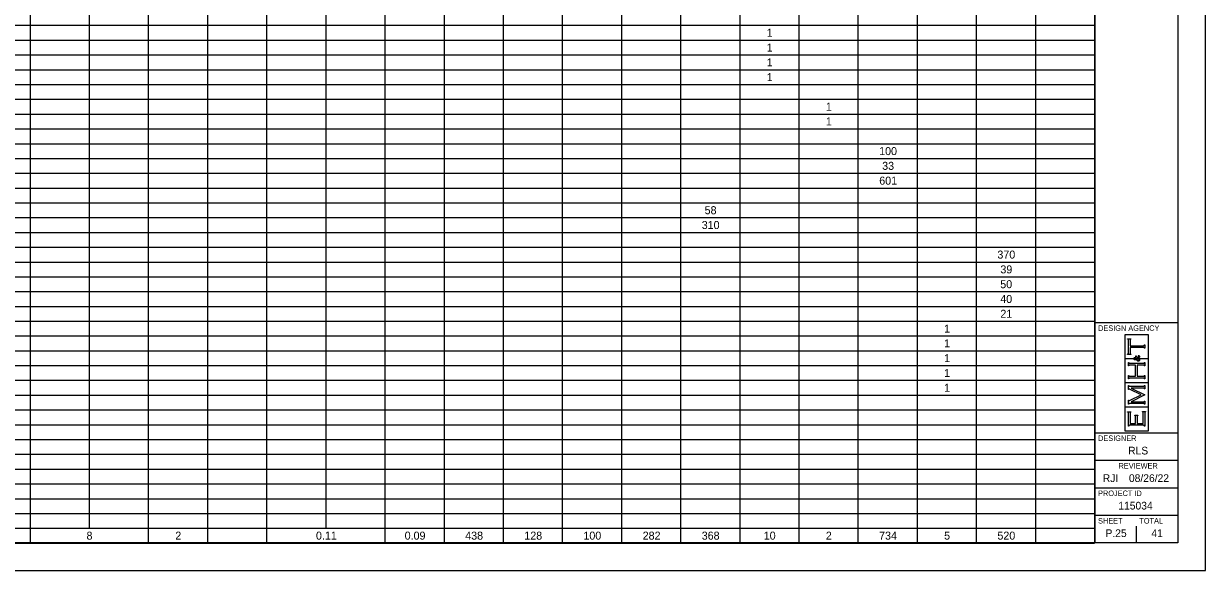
# Model space of a CAD drawing. Extents: x 0 to 34, y 0 to 22.
# Drawn here: x 12.53 to 34, y 0 to 9.93 of the extents above; entities that cross this region are included whole.
import ezdxf

# ---------------------------------------------------------------- set-up
doc = ezdxf.new("R2010")
doc.units = 0
for name, color, linetype in [('SH_Border', 7, 'Continuous'), ('SH_Cut_Line', 7, 'Continuous'), ('SH_Data', 7, 'Continuous'), ('SH_Text', 7, 'Continuous')]:
    doc.layers.add(name, color=color, linetype=linetype)

msp = doc.modelspace()

# ---------------------------------------------------------------- linework, layer by layer
at = {"layer": 'SH_Border'}
for p, q in [((32, 0.5), (32, 21.5)), ((32, 4.5), (33.5, 4.5)), ((32, 2.5), (33.5, 2.5)), ((32, 2), (33.5, 2)), ((32, 1.5), (33.5, 1.5)), ((32, 1), (33.5, 1))]:
    msp.add_line(p, q, dxfattribs=at)
msp.add_lwpolyline([(1.5, 21.5), (33.5, 21.5), (33.5, 0.5), (1.5, 0.5)], close=True, dxfattribs=at)
at = {"layer": 'SH_Cut_Line'}
msp.add_lwpolyline([(0, 0), (34, 0), (34, 22), (0, 22)], close=True, dxfattribs=at)
at = {"layer": 'SH_Data'}
for p, q in [((32.966, 4.28), (32.534, 4.28)), ((32.534, 4.28), (32.534, 3.848)), ((32.588, 4.199), (32.588, 4.206)), ((32.588, 4.206), (32.644, 4.206)), ((32.594, 4.198), (32.588, 4.199)), ((32.598, 4.196), (32.594, 4.198)), ((32.599, 4.194), (32.598, 4.196)), ((32.601, 4.191), (32.599, 4.194)), ((32.602, 4.187), (32.601, 4.191)), ((32.602, 4.181), (32.602, 4.187)), ((32.602, 3.947), (32.602, 4.181)), ((32.632, 4.191), (32.631, 4.187)), ((32.631, 4.187), (32.631, 4.181)), ((32.631, 4.181), (32.631, 4.081)), ((32.631, 4.081), (32.872, 4.081)), ((32.633, 4.194), (32.632, 4.191)), ((32.635, 4.196), (32.633, 4.194)), ((32.639, 4.198), (32.635, 4.196)), ((32.644, 4.199), (32.639, 4.198)), ((32.644, 4.206), (32.644, 4.199)), ((32.872, 4.081), (32.878, 4.081)), ((32.878, 4.081), (32.882, 4.082)), ((32.882, 4.082), (32.885, 4.084)), ((32.885, 4.084), (32.887, 4.085)), ((32.887, 4.085), (32.889, 4.089)), ((32.889, 4.089), (32.891, 4.095)), ((32.891, 4.095), (32.898, 4.095)), ((32.898, 4.095), (32.898, 4.033)), ((32.966, 3.848), (32.966, 4.28)), ((32.588, 3.928), (32.594, 3.93)), ((32.588, 3.921), (32.588, 3.928)), ((32.644, 3.921), (32.588, 3.921)), ((32.594, 3.93), (32.598, 3.932)), ((32.598, 3.932), (32.599, 3.934)), ((32.599, 3.934), (32.601, 3.937)), ((32.601, 3.937), (32.602, 3.941)), ((32.602, 3.941), (32.602, 3.947)), ((32.872, 4.047), (32.631, 4.047)), ((32.631, 4.047), (32.631, 3.947)), ((32.631, 3.947), (32.631, 3.941)), ((32.631, 3.941), (32.632, 3.937)), ((32.632, 3.937), (32.633, 3.934)), ((32.633, 3.934), (32.635, 3.932)), ((32.635, 3.932), (32.639, 3.93)), ((32.639, 3.93), (32.644, 3.928)), ((32.644, 3.928), (32.644, 3.921)), ((32.71, 3.864), (32.714, 3.866)), ((32.714, 3.866), (32.719, 3.866)), ((32.719, 3.866), (32.724, 3.866)), ((32.724, 3.866), (32.728, 3.864)), ((32.738, 3.867), (32.738, 3.898)), ((32.738, 3.898), (32.741, 3.898)), ((32.741, 3.867), (32.738, 3.867)), ((32.741, 3.898), (32.741, 3.894)), ((32.741, 3.894), (32.742, 3.891)), ((32.742, 3.871), (32.741, 3.869)), ((32.741, 3.869), (32.741, 3.867)), ((32.742, 3.891), (32.744, 3.889)), ((32.743, 3.872), (32.742, 3.871)), ((32.745, 3.873), (32.743, 3.872)), ((32.744, 3.889), (32.745, 3.887)), ((32.745, 3.887), (32.75, 3.883)), ((32.747, 3.874), (32.745, 3.873)), ((32.749, 3.874), (32.747, 3.874)), ((32.756, 3.874), (32.749, 3.874)), ((32.75, 3.883), (32.757, 3.879)), ((32.764, 3.87), (32.756, 3.874)), ((32.757, 3.879), (32.765, 3.875)), ((32.775, 3.861), (32.764, 3.87)), ((32.765, 3.875), (32.772, 3.87)), ((32.772, 3.87), (32.779, 3.865)), ((32.779, 3.865), (32.784, 3.869)), ((32.781, 3.9), (32.783, 3.902)), ((32.785, 3.899), (32.781, 3.9)), ((32.783, 3.902), (32.79, 3.901)), ((32.784, 3.869), (32.787, 3.873)), ((32.788, 3.897), (32.785, 3.899)), ((32.787, 3.873), (32.789, 3.876)), ((32.789, 3.895), (32.788, 3.897)), ((32.791, 3.892), (32.789, 3.895)), ((32.789, 3.876), (32.791, 3.88)), ((32.79, 3.901), (32.795, 3.898)), ((32.792, 3.89), (32.791, 3.892)), ((32.791, 3.88), (32.792, 3.883)), ((32.792, 3.886), (32.792, 3.89)), ((32.792, 3.883), (32.792, 3.886)), ((32.795, 3.898), (32.799, 3.894)), ((32.8, 3.868), (32.798, 3.864)), ((32.799, 3.894), (32.802, 3.89)), ((32.802, 3.872), (32.8, 3.868)), ((32.802, 3.89), (32.803, 3.885)), ((32.803, 3.876), (32.802, 3.872)), ((32.803, 3.885), (32.803, 3.88)), ((32.803, 3.88), (32.803, 3.876)), ((32.878, 4.047), (32.872, 4.047)), ((32.883, 4.046), (32.878, 4.047)), ((32.885, 4.044), (32.883, 4.046)), ((32.888, 4.042), (32.885, 4.044)), ((32.889, 4.039), (32.888, 4.042)), ((32.891, 4.033), (32.889, 4.039)), ((32.898, 4.033), (32.891, 4.033)), ((32.534, 3.848), (32.693, 3.848)), ((32.693, 3.842), (32.534, 3.842)), ((32.534, 3.842), (32.534, 3.41)), ((32.602, 3.714), (32.602, 3.776)), ((32.602, 3.776), (32.609, 3.776)), ((32.609, 3.714), (32.602, 3.714)), ((32.609, 3.776), (32.611, 3.77)), ((32.61, 3.72), (32.609, 3.714)), ((32.612, 3.723), (32.61, 3.72)), ((32.611, 3.77), (32.612, 3.766)), ((32.612, 3.766), (32.615, 3.765)), ((32.615, 3.725), (32.612, 3.723)), ((32.615, 3.765), (32.617, 3.763)), ((32.617, 3.727), (32.615, 3.725)), ((32.617, 3.763), (32.622, 3.762)), ((32.622, 3.728), (32.617, 3.727)), ((32.622, 3.762), (32.628, 3.762)), ((32.628, 3.728), (32.622, 3.728)), ((32.628, 3.762), (32.872, 3.762)), ((32.732, 3.728), (32.628, 3.728)), ((32.693, 3.848), (32.693, 3.842)), ((32.701, 3.852), (32.703, 3.857)), ((32.701, 3.846), (32.701, 3.852)), ((32.701, 3.84), (32.701, 3.846)), ((32.703, 3.835), (32.701, 3.84)), ((32.703, 3.857), (32.706, 3.861)), ((32.706, 3.83), (32.703, 3.835)), ((32.706, 3.861), (32.71, 3.864)), ((32.707, 3.852), (32.706, 3.849)), ((32.706, 3.849), (32.706, 3.846)), ((32.706, 3.846), (32.706, 3.842)), ((32.706, 3.842), (32.708, 3.839)), ((32.71, 3.824), (32.706, 3.83)), ((32.71, 3.854), (32.707, 3.852)), ((32.708, 3.839), (32.711, 3.837)), ((32.712, 3.856), (32.71, 3.854)), ((32.717, 3.821), (32.71, 3.824)), ((32.711, 3.837), (32.714, 3.835)), ((32.715, 3.857), (32.712, 3.856)), ((32.714, 3.835), (32.716, 3.834)), ((32.718, 3.857), (32.715, 3.857)), ((32.716, 3.834), (32.719, 3.834)), ((32.725, 3.821), (32.717, 3.821)), ((32.723, 3.857), (32.718, 3.857)), ((32.719, 3.834), (32.722, 3.834)), ((32.722, 3.834), (32.724, 3.834)), ((32.727, 3.856), (32.723, 3.857)), ((32.724, 3.834), (32.727, 3.835)), ((32.728, 3.821), (32.725, 3.821)), ((32.73, 3.853), (32.727, 3.856)), ((32.727, 3.835), (32.73, 3.836)), ((32.728, 3.864), (32.732, 3.861)), ((32.731, 3.822), (32.728, 3.821)), ((32.734, 3.85), (32.73, 3.853)), ((32.73, 3.836), (32.734, 3.837)), ((32.734, 3.822), (32.731, 3.822)), ((32.732, 3.861), (32.736, 3.857)), ((32.732, 3.525), (32.732, 3.728)), ((32.737, 3.845), (32.734, 3.85)), ((32.734, 3.837), (32.74, 3.839)), ((32.737, 3.823), (32.734, 3.822)), ((32.736, 3.857), (32.74, 3.851)), ((32.74, 3.839), (32.737, 3.845)), ((32.741, 3.825), (32.737, 3.823)), ((32.74, 3.851), (32.745, 3.842)), ((32.746, 3.827), (32.741, 3.825)), ((32.745, 3.842), (32.755, 3.848)), ((32.753, 3.815), (32.746, 3.827)), ((32.757, 3.832), (32.751, 3.829)), ((32.751, 3.829), (32.755, 3.824)), ((32.759, 3.808), (32.753, 3.815)), ((32.755, 3.848), (32.765, 3.855)), ((32.755, 3.824), (32.758, 3.819)), ((32.762, 3.835), (32.757, 3.832)), ((32.758, 3.819), (32.762, 3.817)), ((32.765, 3.803), (32.759, 3.808)), ((32.872, 3.728), (32.76, 3.728)), ((32.76, 3.728), (32.76, 3.525)), ((32.766, 3.838), (32.762, 3.835)), ((32.762, 3.817), (32.766, 3.814)), ((32.765, 3.855), (32.775, 3.861)), ((32.77, 3.799), (32.765, 3.803)), ((32.77, 3.84), (32.766, 3.838)), ((32.766, 3.814), (32.771, 3.812)), ((32.776, 3.845), (32.77, 3.84)), ((32.776, 3.797), (32.77, 3.799)), ((32.771, 3.812), (32.775, 3.812)), ((32.775, 3.812), (32.78, 3.812)), ((32.785, 3.851), (32.776, 3.845)), ((32.782, 3.797), (32.776, 3.797)), ((32.78, 3.812), (32.785, 3.814)), ((32.788, 3.797), (32.782, 3.797)), ((32.789, 3.846), (32.785, 3.851)), ((32.785, 3.814), (32.789, 3.817)), ((32.793, 3.8), (32.788, 3.797)), ((32.794, 3.859), (32.789, 3.855)), ((32.789, 3.855), (32.795, 3.849)), ((32.792, 3.842), (32.789, 3.846)), ((32.789, 3.817), (32.793, 3.821)), ((32.793, 3.839), (32.792, 3.842)), ((32.794, 3.837), (32.793, 3.839)), ((32.793, 3.821), (32.795, 3.825)), ((32.797, 3.804), (32.793, 3.8)), ((32.798, 3.864), (32.794, 3.859)), ((32.795, 3.834), (32.794, 3.837)), ((32.795, 3.849), (32.798, 3.843)), ((32.795, 3.831), (32.795, 3.834)), ((32.795, 3.825), (32.795, 3.831)), ((32.801, 3.809), (32.797, 3.804)), ((32.798, 3.843), (32.8, 3.839)), ((32.8, 3.839), (32.802, 3.834)), ((32.803, 3.815), (32.801, 3.809)), ((32.802, 3.834), (32.803, 3.829)), ((32.807, 3.842), (32.803, 3.848)), ((32.803, 3.848), (32.966, 3.848)), ((32.803, 3.829), (32.803, 3.823)), ((32.803, 3.823), (32.803, 3.815)), ((32.966, 3.842), (32.807, 3.842)), ((32.872, 3.762), (32.878, 3.762)), ((32.878, 3.728), (32.872, 3.728)), ((32.878, 3.762), (32.882, 3.763)), ((32.883, 3.727), (32.878, 3.728)), ((32.882, 3.763), (32.885, 3.765)), ((32.885, 3.725), (32.883, 3.727)), ((32.885, 3.765), (32.887, 3.766)), ((32.888, 3.723), (32.885, 3.725)), ((32.887, 3.766), (32.889, 3.77)), ((32.889, 3.72), (32.888, 3.723)), ((32.889, 3.77), (32.891, 3.776)), ((32.891, 3.714), (32.889, 3.72)), ((32.891, 3.776), (32.898, 3.776)), ((32.898, 3.714), (32.891, 3.714)), ((32.898, 3.776), (32.898, 3.714)), ((32.966, 3.41), (32.966, 3.842)), ((32.602, 3.477), (32.602, 3.538)), ((32.602, 3.538), (32.609, 3.538)), ((32.609, 3.477), (32.602, 3.477)), ((32.609, 3.538), (32.611, 3.533)), ((32.61, 3.482), (32.609, 3.477)), ((32.612, 3.486), (32.61, 3.482)), ((32.611, 3.533), (32.612, 3.529)), ((32.612, 3.529), (32.615, 3.527)), ((32.615, 3.488), (32.612, 3.486)), ((32.615, 3.527), (32.617, 3.526)), ((32.617, 3.49), (32.615, 3.488)), ((32.617, 3.526), (32.622, 3.525)), ((32.622, 3.491), (32.617, 3.49)), ((32.622, 3.525), (32.628, 3.525)), ((32.628, 3.491), (32.622, 3.491)), ((32.628, 3.525), (32.732, 3.525)), ((32.872, 3.491), (32.628, 3.491)), ((32.75, 3.5), (32.75, 3.5)), ((32.76, 3.525), (32.872, 3.525)), ((32.872, 3.525), (32.878, 3.525)), ((32.878, 3.491), (32.872, 3.491)), ((32.878, 3.525), (32.883, 3.525)), ((32.883, 3.49), (32.878, 3.491)), ((32.883, 3.525), (32.885, 3.527)), ((32.885, 3.488), (32.883, 3.49)), ((32.885, 3.527), (32.888, 3.529)), ((32.887, 3.486), (32.885, 3.488)), ((32.888, 3.529), (32.889, 3.533)), ((32.889, 3.482), (32.887, 3.486)), ((32.889, 3.533), (32.891, 3.538)), ((32.891, 3.477), (32.889, 3.482)), ((32.891, 3.538), (32.898, 3.538)), ((32.898, 3.477), (32.891, 3.477)), ((32.898, 3.538), (32.898, 3.477)), ((32.534, 3.41), (32.966, 3.41)), ((32.966, 3.405), (32.534, 3.405)), ((32.534, 3.405), (32.534, 2.973)), ((32.602, 3.283), (32.602, 3.36)), ((32.602, 3.36), (32.609, 3.36)), ((32.609, 3.283), (32.602, 3.283)), ((32.609, 3.36), (32.611, 3.354)), ((32.612, 3.29), (32.609, 3.283)), ((32.611, 3.354), (32.612, 3.351)), ((32.612, 3.351), (32.615, 3.349)), ((32.615, 3.293), (32.612, 3.29)), ((32.615, 3.349), (32.617, 3.347)), ((32.618, 3.293), (32.615, 3.293)), ((32.617, 3.347), (32.622, 3.346)), ((32.621, 3.293), (32.618, 3.293)), ((32.626, 3.292), (32.621, 3.293)), ((32.622, 3.346), (32.628, 3.346)), ((32.633, 3.288), (32.626, 3.292)), ((32.628, 3.346), (32.872, 3.346)), ((32.831, 3.189), (32.633, 3.288)), ((32.872, 3.312), (32.649, 3.312)), ((32.649, 3.312), (32.898, 3.186)), ((32.872, 3.346), (32.878, 3.346)), ((32.878, 3.312), (32.872, 3.312)), ((32.878, 3.346), (32.882, 3.347)), ((32.883, 3.311), (32.878, 3.312)), ((32.882, 3.347), (32.885, 3.349)), ((32.885, 3.31), (32.883, 3.311)), ((32.885, 3.349), (32.887, 3.351)), ((32.887, 3.308), (32.885, 3.31)), ((32.887, 3.351), (32.889, 3.354)), ((32.889, 3.304), (32.887, 3.308)), ((32.889, 3.354), (32.891, 3.36)), ((32.891, 3.298), (32.889, 3.304)), ((32.891, 3.36), (32.898, 3.36)), ((32.898, 3.298), (32.891, 3.298)), ((32.898, 3.36), (32.898, 3.298)), ((32.966, 2.973), (32.966, 3.405)), ((32.602, 3.017), (32.602, 3.094)), ((32.602, 3.094), (32.609, 3.094)), ((32.609, 3.017), (32.602, 3.017)), ((32.609, 3.094), (32.612, 3.087)), ((32.61, 3.023), (32.609, 3.017)), ((32.612, 3.026), (32.61, 3.023)), ((32.612, 3.087), (32.615, 3.083)), ((32.615, 3.028), (32.612, 3.026)), ((32.615, 3.083), (32.618, 3.083)), ((32.617, 3.03), (32.615, 3.028)), ((32.622, 3.031), (32.617, 3.03)), ((32.618, 3.083), (32.62, 3.083)), ((32.62, 3.083), (32.625, 3.086)), ((32.628, 3.031), (32.622, 3.031)), ((32.625, 3.086), (32.635, 3.09)), ((32.872, 3.031), (32.628, 3.031)), ((32.635, 3.09), (32.831, 3.189)), ((32.898, 3.186), (32.649, 3.062)), ((32.649, 3.062), (32.872, 3.062)), ((32.872, 3.062), (32.878, 3.062)), ((32.878, 3.031), (32.872, 3.031)), ((32.878, 3.062), (32.882, 3.063)), ((32.883, 3.03), (32.878, 3.031)), ((32.882, 3.063), (32.885, 3.065)), ((32.885, 3.028), (32.883, 3.03)), ((32.885, 3.065), (32.887, 3.067)), ((32.887, 3.026), (32.885, 3.028)), ((32.887, 3.067), (32.889, 3.07)), ((32.889, 3.023), (32.887, 3.026)), ((32.889, 3.07), (32.891, 3.076)), ((32.891, 3.017), (32.889, 3.023)), ((32.891, 3.076), (32.898, 3.076)), ((32.898, 3.017), (32.891, 3.017)), ((32.898, 3.076), (32.898, 3.017)), ((32.534, 2.973), (32.966, 2.973)), ((32.966, 2.967), (32.534, 2.967)), ((32.534, 2.967), (32.534, 2.535)), ((32.588, 2.874), (32.588, 2.881)), ((32.588, 2.881), (32.644, 2.881)), ((32.594, 2.873), (32.588, 2.874)), ((32.598, 2.871), (32.594, 2.873)), ((32.599, 2.868), (32.598, 2.871)), ((32.601, 2.866), (32.599, 2.868)), ((32.602, 2.862), (32.601, 2.866)), ((32.602, 2.856), (32.602, 2.862)), ((32.602, 2.621), (32.602, 2.856)), ((32.632, 2.866), (32.631, 2.862)), ((32.631, 2.862), (32.631, 2.856)), ((32.631, 2.856), (32.631, 2.669)), ((32.633, 2.868), (32.632, 2.866)), ((32.635, 2.871), (32.633, 2.868)), ((32.639, 2.873), (32.635, 2.871)), ((32.644, 2.874), (32.639, 2.873)), ((32.644, 2.881), (32.644, 2.874)), ((32.718, 2.81), (32.718, 2.816)), ((32.718, 2.816), (32.774, 2.816)), ((32.723, 2.808), (32.718, 2.81)), ((32.727, 2.806), (32.723, 2.808)), ((32.729, 2.804), (32.727, 2.806)), ((32.731, 2.801), (32.729, 2.804)), ((32.732, 2.797), (32.731, 2.801)), ((32.732, 2.791), (32.732, 2.797)), ((32.761, 2.801), (32.76, 2.797)), ((32.76, 2.797), (32.76, 2.791)), ((32.763, 2.804), (32.761, 2.801)), ((32.765, 2.806), (32.763, 2.804)), ((32.768, 2.808), (32.765, 2.806)), ((32.774, 2.81), (32.768, 2.808)), ((32.774, 2.816), (32.774, 2.81)), ((32.855, 2.877), (32.855, 2.884)), ((32.855, 2.884), (32.912, 2.884)), ((32.861, 2.876), (32.855, 2.877)), ((32.865, 2.874), (32.861, 2.876)), ((32.867, 2.872), (32.865, 2.874)), ((32.868, 2.869), (32.867, 2.872)), ((32.869, 2.865), (32.868, 2.869)), ((32.869, 2.859), (32.869, 2.865)), ((32.869, 2.669), (32.869, 2.859)), ((32.899, 2.869), (32.898, 2.865)), ((32.898, 2.865), (32.898, 2.858)), ((32.898, 2.858), (32.898, 2.621)), ((32.901, 2.871), (32.899, 2.869)), ((32.903, 2.874), (32.901, 2.871)), ((32.906, 2.876), (32.903, 2.874)), ((32.912, 2.877), (32.906, 2.876)), ((32.912, 2.884), (32.912, 2.877)), ((32.966, 2.535), (32.966, 2.967)), ((32.609, 2.621), (32.602, 2.621)), ((32.611, 2.626), (32.609, 2.621)), ((32.612, 2.63), (32.611, 2.626)), ((32.615, 2.632), (32.612, 2.63)), ((32.617, 2.634), (32.615, 2.632)), ((32.622, 2.635), (32.617, 2.634)), ((32.628, 2.635), (32.622, 2.635)), ((32.872, 2.635), (32.628, 2.635)), ((32.631, 2.669), (32.732, 2.669)), ((32.732, 2.669), (32.732, 2.791)), ((32.76, 2.791), (32.76, 2.669)), ((32.76, 2.669), (32.869, 2.669)), ((32.878, 2.635), (32.872, 2.635)), ((32.883, 2.634), (32.878, 2.635)), ((32.885, 2.632), (32.883, 2.634)), ((32.887, 2.63), (32.885, 2.632)), ((32.889, 2.627), (32.887, 2.63)), ((32.891, 2.621), (32.889, 2.627)), ((32.898, 2.621), (32.891, 2.621)), ((32.534, 2.535), (32.966, 2.535)), ((32.375, 0.675), (32.375, 0.675)), ((32.75, 0.5), (32.75, 0.8))]:
    msp.add_line(p, q, dxfattribs=at)
at = {"layer": 'SH_Text'}
for p, q in [((12.642, 21.5), (12.642, 0.496)), ((13.717, 21.5), (13.717, 0.765)), ((14.791, 21.5), (14.791, 0.496)), ((15.866, 21.5), (15.866, 0.496)), ((16.941, 21.5), (16.941, 0.496)), ((18.015, 21.5), (18.015, 0.765)), ((19.09, 21.5), (19.09, 0.496)), ((20.165, 21.5), (20.165, 0.496)), ((21.239, 21.5), (21.239, 0.496)), ((22.314, 21.5), (22.314, 0.496)), ((23.389, 21.5), (23.389, 0.496)), ((24.463, 21.5), (24.463, 0.496)), ((25.538, 21.5), (25.538, 0.496)), ((26.613, 21.5), (26.613, 0.496)), ((27.687, 21.5), (27.687, 0.496)), ((28.762, 21.5), (28.762, 0.496)), ((29.837, 21.5), (29.837, 0.496)), ((30.911, 21.5), (30.911, 0.496)), ((31.986, 21.5), (31.986, 0.496)), ((1.5, 9.9), (31.986, 9.9)), ((1.5, 9.631), (31.986, 9.631)), ((1.5, 9.362), (31.986, 9.362)), ((1.5, 9.094), (31.986, 9.094)), ((1.5, 8.825), (31.986, 8.825)), ((1.5, 8.556), (31.986, 8.556)), ((1.5, 8.288), (31.986, 8.288)), ((1.5, 8.019), (31.986, 8.019)), ((1.5, 7.75), (31.986, 7.75)), ((1.5, 7.482), (31.986, 7.482)), ((1.5, 7.213), (31.986, 7.213)), ((1.5, 6.944), (31.986, 6.944)), ((1.5, 6.676), (31.986, 6.676)), ((1.5, 6.407), (31.986, 6.407)), ((1.5, 6.138), (31.986, 6.138)), ((1.5, 5.87), (31.986, 5.87)), ((1.5, 5.601), (31.986, 5.601)), ((1.5, 5.332), (31.986, 5.332)), ((1.5, 5.064), (31.986, 5.064)), ((1.5, 4.795), (31.986, 4.795)), ((1.5, 4.526), (31.986, 4.526)), ((1.5, 4.258), (31.986, 4.258)), ((1.5, 3.989), (31.986, 3.989)), ((1.5, 3.72), (31.986, 3.72)), ((1.5, 3.452), (31.986, 3.452)), ((1.5, 3.183), (31.986, 3.183)), ((1.5, 2.914), (31.986, 2.914)), ((1.5, 2.646), (31.986, 2.646)), ((1.5, 2.377), (31.986, 2.377)), ((1.5, 2.108), (31.986, 2.108)), ((1.5, 1.84), (31.986, 1.84)), ((1.5, 1.571), (31.986, 1.571)), ((1.5, 1.302), (31.986, 1.302)), ((1.5, 1.034), (31.986, 1.034)), ((1.5, 0.765), (31.986, 0.765)), ((1.5, 0.496), (31.986, 0.496))]:
    msp.add_line(p, q, dxfattribs=at)

# ---------------------------------------------------------------- texts
at = {"layer": 'SH_Data'}
for s, height, p in [('DESIGN AGENCY', 0.1, (32.05, 4.35)), ('DESIGNER', 0.1, (32.05, 2.35)), ('RLS', 0.14, (32.597, 2.105)), ('REVIEWER', 0.1, (32.422, 1.85)), ('RJI', 0.14, (32.136, 1.605)), ('08/26/22', 0.14, (32.611, 1.605)), ('PROJECT ID', 0.1, (32.05, 1.35)), ('115034', 0.14, (32.418, 1.105)), ('SHEET', 0.1, (32.05, 0.85)), ('TOTAL', 0.1, (32.8, 0.85)), ('P.25', 0.14, (32.185, 0.605)), ('41', 0.14, (33.019, 0.605))]:
    msp.add_text(s, height=height, dxfattribs=at).set_placement(p)
at = {"layer": 'SH_Text'}
for s, height, p in [('1', 0.145, (26.029, 9.693)), ('1', 0.145, (26.029, 9.424)), ('1', 0.145, (26.029, 9.155)), ('1', 0.145, (26.029, 8.887)), ('1', 0.145, (27.103, 8.349)), ('1', 0.145, (27.103, 8.081)), ('100', 0.1454, (28.072, 7.543)), ('33', 0.1454, (28.127, 7.275)), ('601', 0.1454, (28.074, 7.006)), ('58', 0.1454, (24.901, 6.469)), ('310', 0.1454, (24.848, 6.2)), ('370', 0.1454, (30.221, 5.663)), ('39', 0.1454, (30.275, 5.394)), ('50', 0.1454, (30.273, 5.125)), ('40', 0.1454, (30.273, 4.857)), ('21', 0.1454, (30.275, 4.588)), ('1', 0.145, (29.253, 4.319)), ('1', 0.145, (29.253, 4.051)), ('1', 0.145, (29.253, 3.782)), ('1', 0.145, (29.253, 3.513)), ('1', 0.145, (29.253, 3.245)), ('8', 0.145, (13.669, 0.558)), ('2', 0.145, (15.282, 0.558)), ('0.11', 0.1454, (17.838, 0.558)), ('0.09', 0.1454, (19.45, 0.558)), ('438', 0.1454, (20.55, 0.558)), ('128', 0.1454, (21.624, 0.558)), ('100', 0.1454, (22.698, 0.558)), ('282', 0.1454, (23.775, 0.558)), ('368', 0.1454, (24.848, 0.558)), ('10', 0.1454, (25.975, 0.558)), ('2', 0.145, (27.104, 0.558)), ('734', 0.1454, (28.071, 0.558)), ('5', 0.145, (29.253, 0.558)), ('520', 0.1454, (30.221, 0.558))]:
    msp.add_text(s, height=height, dxfattribs=at).set_placement(p)

doc.saveas('drawing.dxf')
